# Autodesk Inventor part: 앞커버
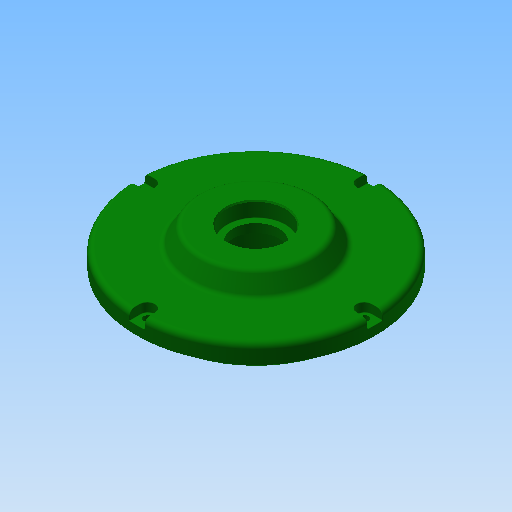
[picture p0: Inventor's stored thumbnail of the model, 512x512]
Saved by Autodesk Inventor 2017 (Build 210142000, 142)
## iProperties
Created: 2016-11
Part Number: 앞커버
Material: 알루미늄 6061
Document SubType Name: Modeling
Designer: mduedu
Density: 2.71 g/cm^3
Mass: 470.684 g
Surface Area: 413.208 cm^2
Volume: 173.684 cm^3
Appearance: 진녹색
Author: mduedu
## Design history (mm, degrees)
sketch "스케치1"
  geometry: L1 (30, -16)-(30, -30); L2 (30, -30)-(20, -35.774); L3 (20, -35.774)-(20, -65); L4 (20, -65)-(10, -65); L5 (10, -65)-(10, -53); L6 (10, -53)-(0, -53); L7 (0, -53)-(0, -23.5); L8 (0, 0)-(30, 0); L9 (14, -23.5)-(14, -20.5); L10 (14, -20.5)-(17, -20.5); L11 (17, -20.5)-(17, -12.5); L12 (0, -23.5)-(14, -23.5); L13 (21.7, -16)-(30, -16); L14 (21.7, -16)-(21.7, -12.5); L15 (21.7, -12.5)-(17, -12.5)
  constraints: 30 end point, 8 parallel, 5 perpendicular, 2 horizontal, 2 vertical alignment
  dimensions: "d0" = 10 distance of L5.end L6.end; "d2" = 10 distance of L3.end L4.end; "d3" = 10 distance between parallel lines of L1 L3; "d4" = 120 deg angle of L3 L2; "d6" = 60 diameter of L1.end L8; "d7" = 41 diameter of L10 L8; "d8" = 47 diameter of L12 L8; "d9" = 32 diameter of L13 L8; "d10" = 106 diameter of L6 L8; "d11" = 130 diameter of L4 L8; "d64" = 14 distance between parallel lines of L9 L7; "d65" = 3 distance of L9.end L10.end; "d66" = 8.3 distance of L13.start L1.start; "d67" = 25 diameter of L15 L8
revolve "회전1" sketch "스케치1" stored, may be unused: angle "d12" = 90 deg
fillet "모깎기1" dims "d13" = 1
fillet "모깎기2" dims "d14" = 3
chamfer "모따기1" distance "d15" = 1; stored, may be unused: second distance "d16" = 2, angle "d17" = 45 deg
fillet "모깎기3" dims "d18" = 0.3
chamfer "모따기2" distance "d36" = 0.8; stored, may be unused: second distance "d37" = 2, angle "d38" = 30 deg
sketch "스케치3"
  geometry: C1 r 65 at (0, 0) reference; A1 r 59 centre (0, 0) between (0, 59) and (59, 0); 2 further points
  constraints: 4 point on circle, 2 horizontal alignment, 2 vertical alignment, 1 centre point, 1 coincident
  dimensions: "d33" = 118 diameter of A1
sketch "스케치4"
  geometry: 4 further points
  constraints: 4 other
hole "구멍2" sketch "스케치4" at (0, 59), (-59, 0), (59, 0), (0, -59) diameter "d39" = 4.5; stored, may be unused: countersink angle "d43" = 90 deg, drill point angle "d45" = 0 deg; dims "d40" = 6, "d41" = 8, "d42" = 5, "d44" = 8
sketch "스케치6"
  geometry: L1 (-4, 5.877)-(-4, 0); L2 (4, 5.877)-(4, 0); A1 r 4 centre (0, 0) between (-2.712, 2.941) and (2.712, 2.941) reference; A2 r 65 centre (0, -59) between (-4, 5.877) and (4, 5.877) reference; 1 further point
  constraints: 4 end point, 4 point on circle, 2 tangent, 2 vertical
extrude "돌출2" cut sketch "스케치6" stored distance "d51" = 10; taper "d52" = 0 deg
fillet "모깎기5" dims "d56" = 0.3
fillet "모깎기6" dims "d57" = 0.3
sketch "스케치5"
  geometry: C1 r 30 at (0, 0); C2 r 47.5 at (0, 0); 1 further point
  constraints: 2 centre point, 2 coincident
  dimensions: "d46" = 60 diameter of C1; "d47" = 95 diameter of C2
extrude "돌출1" cut sketch "스케치5" distance "d48" = 10; taper "d49" = 0 deg
fillet "모깎기4" dims "d50" = 3
node "솔리드1"
pattern_circular "원형 패턴1" dims angle "d54" = 360 deg
pattern_circular "원형 패턴2" dims angle "d59" = 360 deg
pattern_circular "원형 패턴3" dims angle "d62" = 360 deg
